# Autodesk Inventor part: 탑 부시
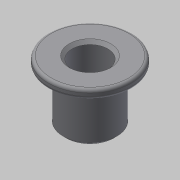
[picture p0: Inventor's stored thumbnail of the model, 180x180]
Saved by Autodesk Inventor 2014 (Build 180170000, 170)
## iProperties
Created: 2016-08
Part Number: 탑 부시
Material: 스테인리스강
Document SubType Name: Modeling
Designer: mduedu
Density: 8.08 g/cm^3
Appearance: 기본값
Author: mduedu
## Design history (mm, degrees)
sketch "스케치1"
  geometry: L1 (0, 0)-(9, 0); L2 (9, 0)-(9, 17); L3 (0, 20)-(0, 0); L4 (9, 17)-(14, 17); L5 (14, 17)-(14, 20); L6 (14, 20)-(0, 20)
  constraints: 12 end point, 2 horizontal, 2 parallel, 2 perpendicular
  dimensions: "d0" = 9 distance between parallel lines of L2 L3; "d2" = 20 distance of L3.start L1.start; "d3" = 14 distance between parallel lines of L5 L3; "d4" = 3 distance of L4.end L5.end
revolve "회전1" sketch "스케치1" stored, may be unused: angle "d5" = 90 deg
hole "구멍1" diameter "d8" = 12; stored, may be unused: countersink angle "d12" = 90 deg, drill point angle "d14" = 118 deg; dims "d6" = 10, "d7" = 10, "d9" = 6, "d10" = 4, "d11" = 2, "d13" = 8
chamfer "모따기1" distance "d15" = 1; stored, may be unused: second distance "d16" = 2, angle "d17" = 45 deg
fillet "모깎기1" dims "d18" = 1
node "솔리드1"
